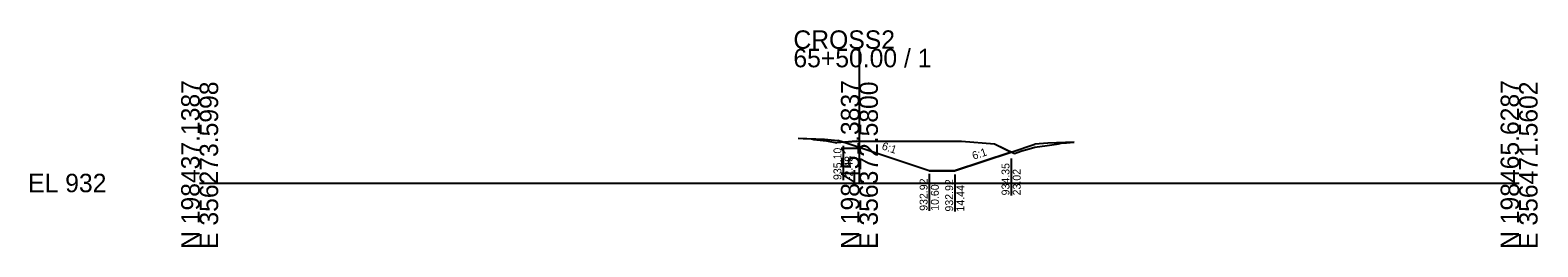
# Model space of a CAD drawing. Extents: x -26 to 203, y -10 to 14021.
# Drawn here: x -25.7 to 202.8, y 6490.3 to 6523.2 of the extents above; entities that cross this region are included whole.
import ezdxf

# ---------------------------------------------------------------- set-up
doc = ezdxf.new("R2010")
doc.units = 0
for name, color, linetype in [('Default', 7, 'Continuous'), ('P_E_XS_Ground', 7, 'Continuous'), ('P_XS', 7, 'Continuous'), ('P_XS_EAR_CommonGrnd', 7, 'Continuous'), ('P_XS_Lane', 7, 'Continuous'), ('P_XS_Rock', 7, 'Continuous')]:
    doc.layers.add(name, color=color, linetype=linetype)

msp = doc.modelspace()

# ---------------------------------------------------------------- linework, layer by layer
at = {"layer": 'Default'}
for p, q in [((100, 6500), (100, 6520.36)), ((0, 6500), (100, 6500)), ((100, 6500), (200, 6500))]:
    msp.add_line(p, q, dxfattribs=at)
at = {"layer": 'P_E_XS_Ground'}
for p, q in [((90.72, 6506.79), (91.5, 6506.76)), ((91.5, 6506.76), (92.74, 6506.7)), ((92.74, 6506.7), (93.1, 6506.61)), ((93.1, 6506.61), (93.54, 6506.55)), ((93.54, 6506.55), (95.01, 6506.39)), ((95.01, 6506.39), (96.56, 6506.12)), ((99.5, 6506.36), (96.56, 6506.12)), ((99.5, 6506.36), (100, 6506.36)), ((100, 6506.36), (115.5, 6506.36)), ((115.5, 6506.36), (120.5, 6505.96)), ((120.5, 6505.96), (123.51, 6504.46)), ((123.51, 6504.46), (124.62, 6504.87)), ((124.62, 6504.87), (125.76, 6505.19)), ((125.76, 6505.19), (126.6, 6505.45)), ((126.6, 6505.45), (128.45, 6505.7)), ((128.45, 6505.7), (129.86, 6505.89)), ((129.86, 6505.89), (130.17, 6505.95)), ((130.17, 6505.95), (130.61, 6506.04)), ((130.61, 6506.04), (131.41, 6506.09)), ((131.41, 6506.09), (132.57, 6506.21))]:
    msp.add_line(p, q, dxfattribs=at)
at = {"layer": 'P_XS'}
for p, q in [((90.72, 6506.79), (94.72, 6506.63)), ((94.72, 6506.63), (96.72, 6506.47)), ((97.52, 6506.2), (96.72, 6506.47)), ((123.02, 6504.7), (126.57, 6505.89)), ((128.57, 6506.05), (126.57, 6505.89)), ((132.57, 6506.21), (128.57, 6506.05))]:
    msp.add_line(p, q, dxfattribs=at)
at = {"layer": 'P_XS_EAR_CommonGrnd'}
msp.add_lwpolyline([(110.6, 6501.84), (97.52, 6506.2), (99.5, 6506.36), (100, 6506.36), (115.5, 6506.36), (120.5, 6505.96), (123.02, 6504.7), (114.44, 6501.84)], close=True, dxfattribs=at)
at = {"layer": 'P_XS_Lane'}
for p, q in [((110.6, 6501.84), (97.52, 6506.2)), ((114.44, 6501.84), (123.02, 6504.7)), ((110.6, 6501.84), (114.44, 6501.84))]:
    msp.add_line(p, q, dxfattribs=at)
at = {"layer": 'P_XS_Rock'}
for p, q in [((97.52, 6505.65), (97.52, 6500.45)), ((123, 6503.71), (123, 6498.11)), ((110.59, 6501.4), (110.59, 6495.78)), ((114.46, 6501.29), (114.46, 6495.67))]:
    msp.add_line(p, q, dxfattribs=at)

# ---------------------------------------------------------------- texts
at = {"layer": 'Default'}
for s, p in [('CROSS2', (90, 6520.36)), ('65+50.00 / 1', (90, 6517.56)), ('EL 932', (-26, 6498.6))]:
    msp.add_text(s, height=2.8, dxfattribs=at).set_placement(p)
for s, p in [('N 198437.1387', (0, 6490)), ('E 356273.5998', (2.8, 6490)), ('N 198451.3837', (100, 6490)), ('E 356372.5800', (102.8, 6490)), ('N 198465.6287', (200, 6490)), ('E 356471.5602', (202.8, 6490))]:
    msp.add_text(s, height=2.8, rotation=90, dxfattribs=at).set_placement(p)
at = {"layer": 'P_XS_Rock'}
for s, rotation, p in [('935.10', 90, (97.27, 6500.45)), ('6:1', 341.5651, (103.3, 6505.13)), ('6:1', 18.4349, (117.32, 6503.52)), ('-2.48', 90, (98.97, 6500.45)), ('934.35', 90, (122.75, 6498.12)), ('23.02', 90, (124.45, 6498.12)), ('932.92', 90, (110.34, 6495.78)), ('10.60', 90, (112.04, 6495.78)), ('932.92', 90, (114.21, 6495.67)), ('14.44', 90, (115.91, 6495.67))]:
    msp.add_text(s, height=1.2, rotation=rotation, dxfattribs=at).set_placement(p)

doc.saveas('drawing.dxf')
